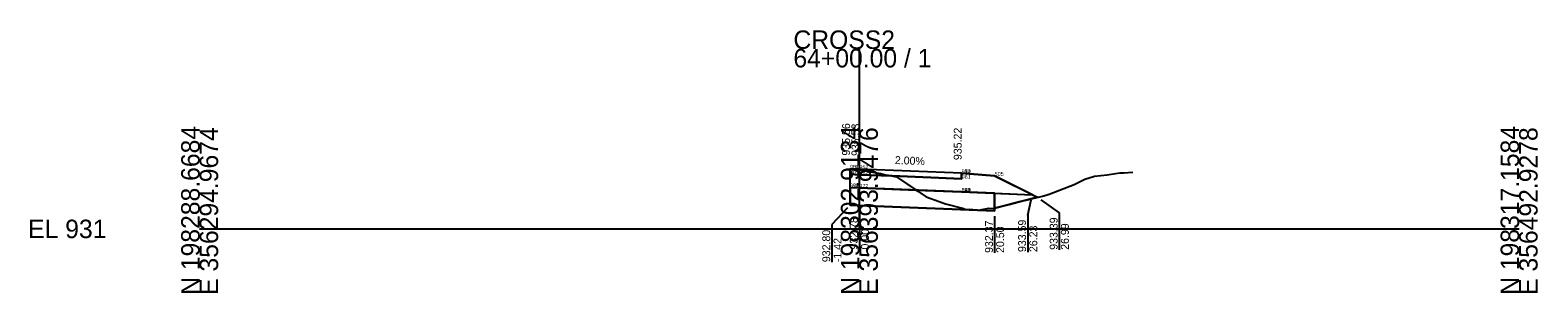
# Model space of a CAD drawing. Extents: x -26 to 203, y -10 to 14021.
# Drawn here: x -25.7 to 202.8, y 4990.3 to 5030.1 of the extents above; entities that cross this region are included whole.
import ezdxf

# ---------------------------------------------------------------- set-up
doc = ezdxf.new("R2010")
doc.units = 0
for name, color, linetype in [('Default', 7, 'Continuous'), ('P_E_XS_Ground', 7, 'Continuous'), ('P_XS', 7, 'Continuous'), ('P_XS_Bold', 7, 'Continuous'), ('P_XS_EAR_CommonGrnd', 7, 'Continuous'), ('P_XS_Lane', 7, 'Continuous'), ('P_XS_Rock', 7, 'Continuous')]:
    doc.layers.add(name, color=color, linetype=linetype)

msp = doc.modelspace()

# ---------------------------------------------------------------- linework, layer by layer
at = {"layer": 'Default'}
for p, q in [((100, 5000), (100, 5027.28)), ((0, 5000), (100, 5000)), ((100, 5000), (200, 5000))]:
    msp.add_line(p, q, dxfattribs=at)
at = {"layer": 'P_E_XS_Ground'}
for p, q in [((98.04, 5009.09), (99.6, 5009.04)), ((99.6, 5009.04), (100.11, 5009)), ((100.11, 5009), (100.8, 5008.8)), ((100.8, 5008.8), (103.25, 5008.38)), ((103.25, 5008.38), (103.95, 5008.21)), ((103.95, 5008.21), (104.38, 5008.15)), ((104.38, 5008.15), (105.63, 5007.88)), ((105.63, 5007.88), (108.84, 5005.72)), ((132.55, 5006.74), (134.17, 5007.56)), ((134.17, 5007.56), (135.62, 5007.98)), ((135.62, 5007.98), (137.57, 5008.2)), ((137.57, 5008.2), (138.83, 5008.39)), ((138.83, 5008.39), (139.48, 5008.5)), ((139.48, 5008.5), (140.08, 5008.51)), ((140.08, 5008.51), (141.46, 5008.62)), ((108.84, 5005.72), (110.12, 5004.87)), ((110.12, 5004.87), (112.1, 5004.17)), ((124.2, 5004.1), (127.94, 5005.03)), ((127.94, 5005.03), (128.77, 5005.28)), ((128.77, 5005.28), (132.55, 5006.74)), ((112.1, 5004.17), (113.07, 5003.82)), ((113.07, 5003.82), (115.61, 5003.15)), ((115.61, 5003.15), (116.18, 5002.95)), ((116.18, 5002.95), (116.74, 5002.97)), ((116.74, 5002.97), (118.05, 5002.85)), ((118.05, 5002.85), (119.62, 5003.15)), ((119.62, 5003.15), (120.35, 5003.11)), ((120.35, 5003.11), (122.7, 5003.69)), ((122.7, 5003.69), (124.2, 5004.1))]:
    msp.add_line(p, q, dxfattribs=at)
at = {"layer": 'P_XS'}
for p, q in [((98.58, 5009.08), (98.58, 5008.28)), ((98.58, 5008.28), (100, 5008.22)), ((98.58, 5006.28), (98.58, 5008.28)), ((115.5, 5007.6), (100, 5008.22)), ((115.5, 5008.43), (115.5, 5007.6)), ((98.58, 5006.28), (100, 5006.22)), ((98.58, 5006.28), (98.58, 5003.61)), ((115.5, 5005.6), (100, 5006.22)), ((115.5, 5005.6), (126.23, 5005.17)), ((120.5, 5005.4), (120.5, 5002.73)), ((98.58, 5003.61), (120.5, 5002.73))]:
    msp.add_line(p, q, dxfattribs=at)
at = {"layer": 'P_XS_EAR_CommonGrnd'}
for points in [[(104.38, 5008.15), (104.99, 5008.02), (115.5, 5007.6), (115.5, 5008.43), (100, 5009.05), (98.58, 5009.11), (98.58, 5009.08), (99.6, 5009.04), (100.11, 5009), (100.8, 5008.8), (103.25, 5008.38), (103.95, 5008.21)], [(104.38, 5008.15), (104.99, 5008.02), (100, 5008.22), (98.58, 5008.28), (98.58, 5009.08), (99.6, 5009.04), (100.11, 5009), (100.8, 5008.8), (103.25, 5008.38), (103.95, 5008.21)], [(98.58, 5008.28), (100, 5008.22), (104.99, 5008.02), (105.63, 5007.88), (108.61, 5005.88), (100, 5006.22), (98.58, 5006.28)], [(120.5, 5005.4), (126.23, 5005.17), (120.5, 5008.03), (115.5, 5008.43), (115.5, 5007.6), (104.99, 5008.02), (105.63, 5007.88), (108.61, 5005.88), (115.5, 5005.6)], [(120.35, 5003.11), (120.5, 5003.14), (120.5, 5002.73), (98.58, 5003.61), (98.58, 5006.28), (100, 5006.22), (108.61, 5005.88), (108.84, 5005.72), (110.12, 5004.87), (112.1, 5004.17), (113.07, 5003.82), (115.61, 5003.15), (116.18, 5002.95), (116.74, 5002.97), (118.05, 5002.85), (119.62, 5003.15)], [(120.35, 5003.11), (120.5, 5003.14), (120.5, 5005.4), (115.5, 5005.6), (108.61, 5005.88), (108.84, 5005.72), (110.12, 5004.87), (112.1, 5004.17), (113.07, 5003.82), (115.61, 5003.15), (116.18, 5002.95), (116.74, 5002.97), (118.05, 5002.85), (119.62, 5003.15)], [(120.5, 5005.4), (126.23, 5005.17), (126.99, 5004.79), (124.2, 5004.1), (122.7, 5003.69), (120.5, 5003.14)]]:
    msp.add_lwpolyline(points, close=True, dxfattribs=at)
at = {"layer": 'P_XS_Lane'}
for p, q in [((100, 5009.05), (98.58, 5009.11)), ((98.58, 5009.11), (98.58, 5009.08)), ((115.5, 5008.43), (100, 5009.05)), ((115.5, 5008.43), (120.5, 5008.03)), ((120.5, 5008.03), (126.99, 5004.79))]:
    msp.add_line(p, q, dxfattribs=at)
at = {"layer": 'P_XS_Rock'}
for p, q in [((98.19, 5003.19), (95.83, 5000.66)), ((125.51, 5002.08), (126.05, 5004.42)), ((127.5, 5004.42), (130.3, 5002.43)), ((95.83, 5000.66), (95.83, 4994.96)), ((100, 5002.46), (100, 4996.87)), ((120.49, 5001.95), (120.49, 4996.36)), ((125.51, 5002.08), (125.51, 4996.49)), ((130.3, 5002.43), (130.3, 4996.83))]:
    msp.add_line(p, q, dxfattribs=at)

# ---------------------------------------------------------------- texts
at = {"layer": 'Default'}
for s, p in [('CROSS2', (90, 5027.28)), ('64+00.00 / 1', (90, 5024.48)), ('EL 931', (-26, 4998.6))]:
    msp.add_text(s, height=2.8, dxfattribs=at).set_placement(p)
for s, p in [('N 198288.6684', (0, 4990)), ('E 356294.9674', (2.8, 4990)), ('N 198302.9134', (100, 4990)), ('E 356393.9476', (102.8, 4990)), ('N 198317.1584', (200, 4990)), ('E 356492.9278', (202.8, 4990))]:
    msp.add_text(s, height=2.8, rotation=90, dxfattribs=at).set_placement(p)
at = {"layer": 'P_XS_Bold'}
for s, p in [('951', (98.58, 5009.11)), ('9', (98.58, 5009.11)), ('900', (98.58, 5009.11)), ('952', (100, 5009.05)), ('952', (100, 5009.05)), ('961', (98.58, 5008.28)), ('962', (100, 5008.22)), ('962', (100, 5008.22)), ('951', (115.5, 5008.43)), ('9', (115.5, 5008.43)), ('900', (115.5, 5008.43)), ('910', (115.5, 5008.43)), ('961', (115.5, 5007.6)), ('505', (120.5, 5008.03)), ('971', (98.58, 5006.28)), ('998', (98.58, 5006.28)), ('972', (100, 5006.22)), ('972', (100, 5006.22)), ('540', (115.5, 5005.6)), ('971', (115.5, 5005.6)), ('998', (115.5, 5005.6))]:
    msp.add_text(s, height=0.6, dxfattribs=at).set_placement(p)
at = {"layer": 'P_XS_Rock'}
for s, rotation, p in [('935.56', 90, (98.58, 5011.11)), ('935.53', 90, (100, 5011.05)), ('935.53', 90, (100, 5011.05)), ('935.53', 90, (100, 5011.05)), ('935.53', 90, (100, 5011.05)), ('935.22', 90, (115.5, 5010.43)), ('2.00%', 357.7094, (105.36, 5009.84)), ('932.78', 90, (99.75, 4996.87)), ('932.37', 90, (120.24, 4996.36)), ('20.50', 90, (121.94, 4996.36)), ('933.59', 90, (125.26, 4996.49)), ('26.23', 90, (126.96, 4996.49)), ('933.39', 90, (130.05, 4996.83)), ('26.99', 90, (131.75, 4996.83)), ('932.80', 90, (95.58, 4994.96)), ('-1.42', 90, (97.28, 4994.96)), ('0.00', 90, (101.45, 4996.87))]:
    msp.add_text(s, height=1.2, rotation=rotation, dxfattribs=at).set_placement(p)

doc.saveas('drawing.dxf')
